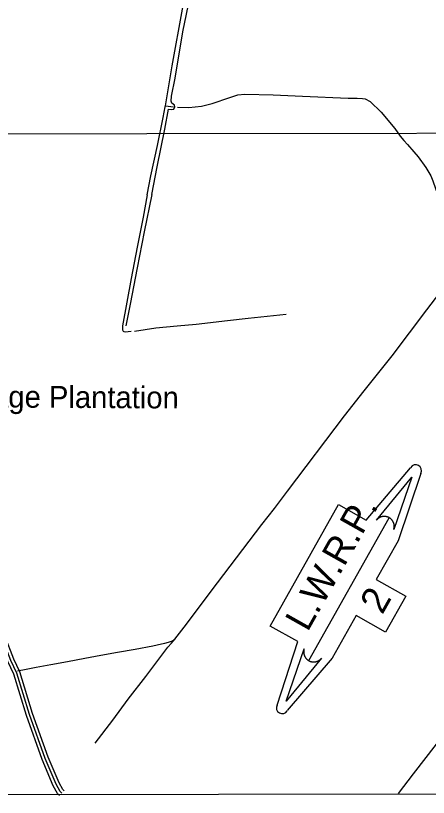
# Model space of a CAD drawing. Extents: x 3297735 to 3335592, y 670436 to 695807.
# Drawn here: x 3314450 to 3316340, y 675812 to 679392 of the extents above; entities that cross this region are included whole.
import ezdxf

# ---------------------------------------------------------------- set-up
doc = ezdxf.new("R2010")
doc.units = 0
for name, color, linetype in [('V-BLDG-IDEN', 7, 'Continuous'), ('V-DTCH-CNTR', 7, 'Continuous'), ('V-GRID-FRAM', 7, 'Continuous'), ('V-GRID-MAJR', 7, 'Continuous'), ('V-ROAD-CNTR', 7, 'Continuous'), ('V-TOPO-SHOR', 7, 'Continuous'), ('V-TOPO-WATR-IDEN', 7, 'Continuous')]:
    doc.layers.add(name, color=color, linetype=linetype)

msp = doc.modelspace()

# ---------------------------------------------------------------- linework, layer by layer
at = {"layer": 'V-DTCH-CNTR'}
for points in [[(3315074.1, 678573.2), (3315098.5, 678700.3), (3315132.7, 678872.1), (3315149.9, 678964.3), (3315162.2, 678962.4), (3315175.1, 678964.1), (3315178.9, 678974.3), (3315177.7, 678982.9), (3315165.8, 678991.8), (3315161.8, 679001.1), (3315163.6, 679024.3), (3315179.8, 679105.9), (3315215.6, 679318), (3315291.9, 679688.3), (3315329.6, 679871.5), (3315347.3, 679946.5)], [(3315074.1, 678573.2), (3315039.1, 678402), (3315006.3, 678237), (3314974.8, 678070.5), (3314955, 677972)]]:
    msp.add_lwpolyline(points, dxfattribs=at)
at = {"layer": 'V-GRID-FRAM'}
msp.add_lwpolyline([(3301851.4, 693996.5), (3333375, 694028.6), (3333401.5, 675844.1), (3301862, 675812)], close=True, dxfattribs=at)
at = {"layer": 'V-GRID-MAJR'}
msp.add_lwpolyline([(3301860.2, 678842.7), (3303311.9, 678843.6), (3306791, 678845.9), (3310174.4, 678848.5), (3313813, 678851.6), (3318760.4, 678856.5), (3322367.1, 678860.5), (3326388.7, 678865.3), (3330442.3, 678870.6), (3332389.2, 678873.4), (3333397.1, 678874.8)], dxfattribs=at)
at = {"layer": 'V-ROAD-CNTR'}
for points in [[(3314661.5, 675830.9), (3314653.6, 675838.8), (3314635.1, 675871.7), (3314584.9, 675990.3), (3314513.3, 676191.7), (3314455.1, 676381), (3314428.1, 676439.5), (3314386.8, 676546.2), (3314292.5, 676823), (3314211.6, 677061.7), (3314148.4, 677239.4), (3314106, 677380.9), (3314079.9, 677450.9), (3314048.7, 677512.5)], [(3314672.1, 675841.5), (3314665.6, 675847.9), (3314648.5, 675878.3), (3314598.9, 675995.7), (3314527.5, 676196.4), (3314469.2, 676386.4), (3314441.9, 676445.3), (3314400.9, 676551.4), (3314306.7, 676827.8), (3314225.8, 677066.6), (3314162.7, 677244.1), (3314120.3, 677385.7), (3314093.7, 677456.9), (3314062, 677519.3)], [(3314650.9, 675820.3), (3314641.5, 675829.6), (3314621.6, 675865), (3314570.9, 675984.8), (3314499, 676186.9), (3314441.1, 676375.6), (3314414.3, 676433.6), (3314372.7, 676541.1), (3314278.3, 676818.1), (3314197.5, 677056.8), (3314134.2, 677234.8), (3314091.8, 677376.1), (3314069.2, 677436.6)]]:
    msp.add_lwpolyline(points, dxfattribs=at)
at = {"layer": 'V-TOPO-SHOR'}
for p, q in [((3315763.4, 679024.1), (3315972.6, 679015.1)), ((3315136, 678979.3), (3315173.6, 678974.9))]:
    msp.add_line(p, q, dxfattribs=at)
for points in [[(3315136, 678979.3), (3315167.4, 679163), (3315214.2, 679422.2), (3315263.3, 679673.5), (3315309.2, 679887.3), (3315327.4, 679959.5), (3315376.8, 679952.9)], [(3315190.5, 678973.5), (3315243, 678971.6), (3315301.3, 678977.6), (3315349.7, 678990.1), (3315431.3, 679017), (3315467.7, 679029.5), (3315499.4, 679032.1), (3315629.8, 679030), (3315763.4, 679024.1)], [(3315972.6, 679015.1), (3316014.2, 679015.1), (3316039, 679013.1), (3316051.1, 679011.1), (3316073.9, 678999), (3316123.6, 678950.1), (3316186.6, 678875), (3316211.5, 678840.2), (3316227.6, 678820.1), (3316245, 678802), (3316274.5, 678769.1), (3316294, 678745), (3316328.9, 678696.7), (3316351, 678659.2), (3316361.1, 678635.7), (3316372.5, 678600.2), (3316388, 678557.9), (3316400.7, 678523.7), (3316411.5, 678495.6), (3316423.6, 678472.8)], [(3315051.7, 678571.8), (3315069, 678658.1), (3315099.6, 678798.2), (3315125.9, 678925.3), (3315135.3, 678975.1), (3315136, 678979.3)], [(3315051.7, 678571.8), (3315034.3, 678469.9), (3315006.5, 678332.6), (3314978.9, 678188.7), (3314958.9, 678079.4), (3314939.6, 677971.5), (3314938.6, 677953.5), (3314941.6, 677946.5), (3314945.4, 677945.3), (3314951.6, 677944.9), (3314978.5, 677946.6)], [(3315694.8, 677214.7), (3315956.4, 677559.8), (3316046.8, 677674.1), (3316174, 677834), (3316333.3, 678045.7), (3316472.9, 678227.2)], [(3314994.9, 677948), (3315092.2, 677962.9), (3315189.4, 677971.7), (3315276.5, 677979.9), (3315420.1, 677996.1), (3315514.3, 678007), (3315688.9, 678025.1)], [(3316204.1, 675829.5), (3316272.5, 675919.1), (3316377.3, 676055), (3316515.3, 676235.7), (3316657.7, 676419.1), (3316712.5, 676489.4), (3316730.2, 676517.4), (3316736.7, 676536.3), (3316738, 676557.2), (3316733.7, 676603.9), (3316731.2, 676632.8), (3316737.8, 676659.3), (3316778.5, 676708.7), (3316882.3, 676815.4), (3317026.3, 676959.7), (3317181.5, 677107.4), (3317336.4, 677269.4), (3317467.2, 677393.2), (3317608.4, 677535.1), (3317721.7, 677646.1), (3317820.7, 677748.8), (3317957.1, 677880.5), (3318064, 677987.9)], [(3314458.9, 676391.6), (3314497.9, 676399.8), (3314544.3, 676407.6), (3314611.6, 676420.3), (3314686.8, 676434.6), (3314766.8, 676449.9), (3314839.9, 676463.8), (3314916.2, 676477.2), (3314997.5, 676491.3), (3315078, 676506.6), (3315118.2, 676515.3), (3315132.6, 676517.5), (3315149.9, 676522.1), (3315168.4, 676529.6), (3315179.6, 676535.9), (3315221, 676590.9), (3315374.4, 676794.8), (3315577.5, 677061.3), (3315635.7, 677135.5), (3315694.8, 677214.7)], [(3314813.5, 676059.6), (3314895.6, 676164.9), (3314965.6, 676262.3), (3315046, 676365.6), (3315119.8, 676462.9), (3315147.4, 676499.7), (3315163.7, 676517.8), (3315179.6, 676535.9)]]:
    msp.add_lwpolyline(points, dxfattribs=at)
at = {"layer": 'V-TOPO-WATR-IDEN'}
msp.add_line((3315792.6, 676438.2), (3316160.8, 677092.9), dxfattribs=at)
for points in [[(3315647.9, 676235), (3315741.7, 676525.7), (3315615.6, 676596.7), (3315928.6, 677153.2), (3316054.8, 677082.3), (3316259.3, 677322)], [(3316305.5, 677296), (3316201.6, 676987.5), (3316101.9, 676810.2), (3316237.3, 676734.1), (3316144.6, 676569.3), (3316009.2, 676645.4), (3315899, 676449.5), (3315694.1, 676209.1)]]:
    msp.add_lwpolyline(points, dxfattribs=at)
for points in [[(3316103.2, 677082.3), (3316265, 677278), (3316181.7, 677038.2), (3316182.9, 677042.5), (3316183.7, 677046.9), (3316183.9, 677048.6), (3316184.1, 677050.2), (3316184.1, 677052.1), (3316184.1, 677053.9), (3316184.1, 677055.5), (3316183.9, 677057.7), (3316183.6, 677060), (3316183.4, 677061.3), (3316183.1, 677062.9), (3316182.5, 677065.1), (3316182.1, 677066.7), (3316181.5, 677068.5), (3316181, 677069.6), (3316180.5, 677070.9), (3316179.9, 677072.4), (3316179.2, 677073.7), (3316178.5, 677075), (3316177.9, 677076.1), (3316177, 677077.7), (3316176, 677079.1), (3316175.2, 677080.3), (3316174.2, 677081.6), (3316173.2, 677082.7), (3316172.4, 677083.6), (3316171.7, 677084.4), (3316170.7, 677085.5), (3316169.6, 677086.5), (3316168.5, 677087.5), (3316167.3, 677088.5), (3316166.3, 677089.3), (3316165, 677090.2), (3316164, 677090.9), (3316162.5, 677091.9), (3316160.8, 677092.9), (3316160.3, 677093.2), (3316159.5, 677093.6), (3316158.5, 677094.1), (3316157.5, 677094.6), (3316156.6, 677095), (3316155.6, 677095.4), (3316154.5, 677095.8), (3316153.8, 677096.1), (3316152.6, 677096.5), (3316151.5, 677096.9), (3316150.8, 677097.1), (3316148.8, 677097.6), (3316147.8, 677097.8), (3316147, 677098), (3316145.8, 677098.2), (3316144.7, 677098.3), (3316143.6, 677098.5), (3316142.3, 677098.6), (3316141, 677098.7), (3316140, 677098.8), (3316139.2, 677098.8), (3316138, 677098.8), (3316137, 677098.8), (3316135.8, 677098.7), (3316134.6, 677098.6), (3316133.4, 677098.5), (3316131.9, 677098.3), (3316130.8, 677098.1), (3316129.6, 677097.9), (3316128.4, 677097.7), (3316127.4, 677097.4), (3316126.4, 677097.2), (3316124.9, 677096.7), (3316124.8, 677096.7), (3316124, 677096.4), (3316123.3, 677096.2), (3316122.3, 677095.9), (3316121.1, 677095.4), (3316120.2, 677095), (3316119.4, 677094.6), (3316118.3, 677094.1), (3316117.3, 677093.6), (3316116.6, 677093.2), (3316115.6, 677092.7), (3316114.4, 677092), (3316113.6, 677091.5), (3316113.1, 677091.1), (3316112.6, 677090.8), (3316111.9, 677090.4), (3316111.1, 677089.8), (3316110.4, 677089.2), (3316109.6, 677088.6), (3316108.9, 677088), (3316107.9, 677087.1), (3316107.4, 677086.6), (3316106.5, 677085.8), (3316105.5, 677084.8), (3316104.8, 677084.1), (3316104.3, 677083.5), (3316103.8, 677083), (3316103.5, 677082.6)], [(3315850.2, 676448.8), (3315688.4, 676253.1), (3315771.7, 676492.9), (3315770.5, 676488.5), (3315769.7, 676484.2), (3315769.4, 676482.4), (3315769.3, 676480.9), (3315769.2, 676479), (3315769.2, 676477.2), (3315769.3, 676475.6), (3315769.5, 676473.4), (3315769.8, 676471.1), (3315770, 676469.8), (3315770.3, 676468.2), (3315770.8, 676466), (3315771.3, 676464.4), (3315771.9, 676462.6), (3315772.3, 676461.5), (3315772.9, 676460.2), (3315773.5, 676458.7), (3315774.2, 676457.4), (3315774.9, 676456), (3315775.5, 676455), (3315776.4, 676453.4), (3315777.4, 676451.9), (3315778.2, 676450.8), (3315779.2, 676449.5), (3315780.1, 676448.4), (3315781, 676447.4), (3315781.7, 676446.7), (3315782.7, 676445.6), (3315783.8, 676444.6), (3315784.9, 676443.6), (3315786, 676442.6), (3315787.1, 676441.8), (3315788.3, 676440.9), (3315789.4, 676440.2), (3315790.9, 676439.2), (3315792.6, 676438.2), (3315793.1, 676437.9), (3315793.9, 676437.4), (3315794.9, 676436.9), (3315795.9, 676436.5), (3315796.8, 676436.1), (3315797.7, 676435.7), (3315798.9, 676435.2), (3315799.6, 676435), (3315800.8, 676434.6), (3315801.9, 676434.2), (3315802.6, 676434), (3315804.6, 676433.5), (3315805.6, 676433.3), (3315806.4, 676433.1), (3315807.6, 676432.9), (3315808.6, 676432.7), (3315809.8, 676432.6), (3315811.1, 676432.5), (3315812.4, 676432.4), (3315813.4, 676432.3), (3315814.2, 676432.3), (3315815.3, 676432.3), (3315816.4, 676432.3), (3315817.6, 676432.4), (3315818.8, 676432.5), (3315820, 676432.6), (3315821.5, 676432.8), (3315822.6, 676432.9), (3315823.8, 676433.2), (3315825, 676433.4), (3315826, 676433.6), (3315827, 676433.9), (3315828.5, 676434.3), (3315828.5, 676434.4), (3315829.4, 676434.6), (3315830.1, 676434.9), (3315831.1, 676435.2), (3315832.3, 676435.7), (3315833.2, 676436.1), (3315834, 676436.5), (3315835.1, 676437), (3315836.1, 676437.5), (3315836.8, 676437.9), (3315837.8, 676438.4), (3315839, 676439.1), (3315839.8, 676439.6), (3315840.3, 676440), (3315840.8, 676440.3), (3315841.5, 676440.7), (3315842.2, 676441.3), (3315843, 676441.9), (3315843.8, 676442.5), (3315844.5, 676443.1), (3315845.5, 676443.9), (3315846, 676444.4), (3315846.9, 676445.3), (3315847.9, 676446.2), (3315848.6, 676447), (3315849.1, 676447.6), (3315849.6, 676448.1), (3315849.9, 676448.5)]]:
    msp.add_lwpolyline(points, close=True, dxfattribs=at)
for centre, start, end in [((3316282.4, 677309), 330.6427, 150.6427), ((3315671, 676222), 150.6427, 330.6427)]:
    msp.add_arc(centre, 26.5, start, end, dxfattribs=at)

# ---------------------------------------------------------------- texts
at = {"layer": 'V-BLDG-IDEN'}
msp.add_text('Cottage Plantation', height=100, rotation=359.6879, dxfattribs=at).set_placement((3314096.5, 677599))
at = {"layer": 'V-TOPO-WATR-IDEN'}
for s, rotation, p in [('L.W.R.P.', 60.6426, (3315787.2, 676566.4)), ('2', 60.6427, (3316129.5, 676645.6))]:
    msp.add_text(s, height=124.5, rotation=rotation, dxfattribs=at).set_placement(p)

doc.saveas('drawing.dxf')
